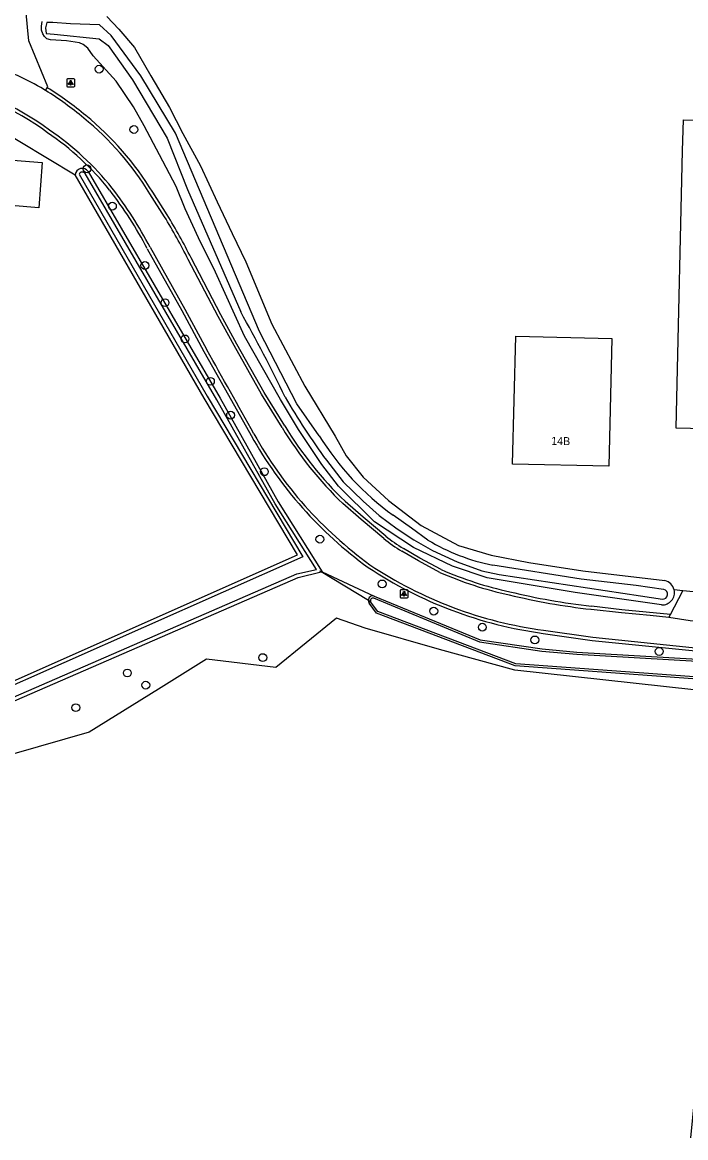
# Model space of a CAD drawing. Extents: x 162515 to 163909, y 388494 to 389773.
# Drawn here: x 162882.1 to 162964.9, y 388907.6 to 389047 of the extents above; entities that cross this region are included whole.
import ezdxf

# ---------------------------------------------------------------- set-up
doc = ezdxf.new("R2010")
doc.units = 0
for name, color, linetype in [('IMGEO_Boom', 7, 'Continuous'), ('IMGEO_Duiker', 7, 'Continuous'), ('IMGEO_Erf', 7, 'Continuous'), ('IMGEO_Grasland_overig', 7, 'Continuous'), ('IMGEO_Lichtpunt', 7, 'Continuous'), ('IMGEO_Pand', 7, 'Continuous'), ('IMGEO_Pand_nummerreeks', 7, 'Continuous'), ('IMGEO_Rijbaan_lokaal_gesloten', 7, 'Continuous'), ('IMGEO_Rijbaan_lokaal_halfverhard', 7, 'Continuous'), ('IMGEO_Rijbaan_lokaal_open', 7, 'Continuous'), ('IMGEO_Waterloop', 7, 'Continuous')]:
    doc.layers.add(name, color=color, linetype=linetype)

msp = doc.modelspace()

# ---------------------------------------------------------------- linework, layer by layer
at = {"layer": 'IMGEO_Boom'}
for centre in [(162891.65, 389041.11), (162895.99, 389033.56), (162890.14, 389028.65), (162893.31, 389023.99), (162897.37, 389016.57), (162899.88, 389011.92), (162902.38, 389007.39), (162905.55, 389002.09), (162908.07, 388997.86), (162912.28, 388990.79), (162919.22, 388982.36), (162927, 388976.77), (162933.44, 388973.37), (162939.51, 388971.36), (162946.06, 388969.77), (162912.09, 388967.56), (162961.59, 388968.33), (162895.18, 388965.64), (162897.48, 388964.12), (162888.74, 388961.31)]:
    msp.add_circle(centre, 0.489, dxfattribs=at)
at = {"layer": 'IMGEO_Duiker'}
msp.add_lwpolyline([(162925.55, 388974.52), (162925.28, 388974.68), (162919.38, 388978.26), (162919.23, 388978.35)], dxfattribs=at)
at = {"layer": 'IMGEO_Erf'}
for points in [[(162892.6, 389047.68), (162894.1, 389046.11), (162896.08, 389043.82), (162898.1, 389040.29), (162900.44, 389036.33), (162902.12, 389033.05), (162904.3, 389029.04), (162906.41, 389024.54), (162908.27, 389020.57), (162909.99, 389017.04), (162913.23, 389009.24), (162917.33, 389001.49), (162921.11, 388995.24), (162922.51, 388992.78), (162924.64, 388990.11), (162927.8, 388987.2), (162931.87, 388984.07), (162936.51, 388981.57), (162940.61, 388980.35), (162945.32, 388979.43), (162952.05, 388978.4), (162962.29, 388977.18)], [(162816.85, 388961.05), (162821.19, 388960.92), (162824.39, 388960.76), (162843.87, 388960.07), (162877.14, 388962.94), (162916.43, 388980.39), (162904.76, 389000), (162888.66, 389027.91)]]:
    msp.add_lwpolyline(points, dxfattribs=at)
msp.add_arc((162961.96, 388975.68), 1.54, 12.9757, 77.6155, dxfattribs=at)
at = {"layer": 'IMGEO_Grasland_overig'}
for points in [[(162961.88, 388974.14), (162951.1, 388975.68), (162940.13, 388977.51), (162935.78, 388978.99), (162930.9, 388981.31), (162926.02, 388984.51), (162921.54, 388989), (162919.45, 388991.71), (162916.57, 388996.05), (162914.29, 388999.84), (162909.82, 389007.73), (162906.18, 389015.74), (162904.05, 389020.03), (162902.41, 389023.63), (162901.28, 389026.43), (162899.19, 389030.38), (162897.29, 389034.04), (162895.94, 389036.38), (162893.79, 389039.62), (162890.91, 389042.76), (162890.23, 389043.72), (162889.65, 389044.2), (162889.21, 389044.4), (162887.56, 389044.65), (162885.56, 389044.78), (162885.13, 389044.91), (162884.83, 389045.18), (162884.63, 389045.54), (162884.47, 389045.97), (162884.45, 389046.48), (162884.52, 389047.05)], [(162878.25, 389034.16), (162888.66, 389027.91)], [(162890.27, 389028.32), (162906.76, 389000), (162914.02, 388987.02), (162919.52, 388978.29)], [(162874.43, 388960.34), (162877.49, 388960.62), (162916.5, 388977.59), (162919.38, 388978.26), (162919.52, 388978.29)], [(162919.52, 388978.29), (162925.98, 388975.25)], [(162925.98, 388975.25), (162939.23, 388969.78), (162946.96, 388968.64), (162951.32, 388968.25), (162966.39, 388967.36), (162970.78, 388966.26), (162971.31, 388964.52), (162972.19, 388961.62)], [(162964.53, 388975.92), (162963.46, 388976.02)], [(162969.72, 388963.11), (162969.19, 388964.66), (162943.62, 388966.52), (162926.27, 388973.12), (162925.38, 388974.38)], [(162969.72, 388963.11), (162943.58, 388965.98), (162934.15, 388968.56), (162924.89, 388971.24), (162921.31, 388972.48), (162913.72, 388966.33), (162905.08, 388967.36), (162899.05, 388963.63), (162890.42, 388958.22), (162881.01, 388955.53), (162875.05, 388956.02), (162874.43, 388960.34)]]:
    msp.add_lwpolyline(points, dxfattribs=at)
for centre, radius, start, end in [((162889.54, 389027.83), 0.884, 33.4629, 174.7096), ((162925.84, 388974.71), 0.565, 75.6448, 182.3466), ((162961.96, 388975.68), 1.54, 267.0987, 12.9137), ((162925.84, 388974.71), 0.565, 182.2245, 214.8736)]:
    msp.add_arc(centre, radius, start, end, dxfattribs=at)
at = {"layer": 'IMGEO_Lichtpunt'}
for p, q in [((162887.61, 389039.81), (162887.61, 389039)), ((162887.61, 389039.81), (162887.61, 389039)), ((162888.51, 389039.9), (162887.7, 389039.9)), ((162888.51, 389039.9), (162887.7, 389039.9)), ((162888.61, 389039), (162888.61, 389039.81)), ((162888.61, 389039), (162888.61, 389039.81)), ((162887.7, 389038.91), (162888.51, 389038.91)), ((162887.7, 389038.91), (162888.51, 389038.91)), ((162929.24, 388975.94), (162929.24, 388975.13)), ((162929.24, 388975.94), (162929.24, 388975.13)), ((162930.14, 388976.03), (162929.33, 388976.03)), ((162930.14, 388976.03), (162929.33, 388976.03)), ((162929.33, 388975.04), (162930.14, 388975.04)), ((162929.33, 388975.04), (162930.14, 388975.04)), ((162930.23, 388975.13), (162930.23, 388975.94)), ((162930.23, 388975.13), (162930.23, 388975.94))]:
    msp.add_line(p, q, dxfattribs=at)
for points in [[(162887.98, 389039.47), (162888.02, 389039.45), (162887.84, 389039.18), (162887.8, 389039.21), (162887.98, 389039.47)], [(162888.09, 389039.43), (162888.13, 389039.43), (162888.13, 389039.1), (162888.09, 389039.1), (162888.09, 389039.43)], [(162888.2, 389039.45), (162888.23, 389039.47), (162888.42, 389039.21), (162888.38, 389039.18), (162888.2, 389039.45)], [(162929.61, 388975.6), (162929.65, 388975.57), (162929.46, 388975.31), (162929.42, 388975.34), (162929.61, 388975.6)], [(162929.71, 388975.55), (162929.76, 388975.55), (162929.76, 388975.23), (162929.71, 388975.23), (162929.71, 388975.55)], [(162929.82, 388975.57), (162929.86, 388975.6), (162930.05, 388975.34), (162930.01, 388975.31), (162929.82, 388975.57)]]:
    msp.add_lwpolyline(points, dxfattribs=at)
for centre in [(162888.11, 389039.61), (162929.74, 388975.74)]:
    msp.add_circle(centre, 0.0994, dxfattribs=at)
for centre, start, end in [((162887.7, 389039.81), 90, 180), ((162887.7, 389039.81), 90, 180), ((162887.7, 389039), 180, 270), ((162887.7, 389039), 180, 270), ((162888.51, 389039.81), 0, 90), ((162888.51, 389039.81), 0, 90), ((162888.51, 389039), 270, 0), ((162888.51, 389039), 270, 360), ((162929.33, 388975.94), 90, 180), ((162929.33, 388975.94), 90, 180), ((162929.33, 388975.13), 180, 270), ((162929.33, 388975.13), 180, 270), ((162930.14, 388975.94), 0, 90), ((162930.14, 388975.94), 0, 90), ((162930.14, 388975.13), 270, 0), ((162930.14, 388975.13), 270, 360)]:
    msp.add_arc(centre, 0.0946, start, end, dxfattribs=at)
at = {"layer": 'IMGEO_Pand'}
for points in [[(162964.61, 389034.78), (162973.6, 389034.57), (162973.51, 389030.67), (162972.8, 389000), (162972.71, 388996.01), (162963.71, 388996.22), (162963.8, 389000), (162964.52, 389030.88), (162964.61, 389034.78)], [(162867.03, 389021.53), (162867.2, 389023.58), (162863, 389023.94), (162863.17, 389026.12), (162863.56, 389031.1), (162884.55, 389029.46), (162884.11, 389023.77), (162876.68, 389024.39), (162876.61, 389023.5), (162874.12, 389023.71), (162873.89, 389020.95), (162868.91, 389021.37), (162867.03, 389021.53)], [(162955.68, 389007.46), (162955.3, 388991.47), (162943.29, 388991.75), (162943.67, 389007.75), (162955.68, 389007.46)]]:
    msp.add_lwpolyline(points, dxfattribs=at)
at = {"layer": 'IMGEO_Rijbaan_lokaal_gesloten'}
for points in [[(162884.97, 389038.44), (162884.37, 389038.8)], [(162899.81, 389022.67), (162898, 389025.53)], [(162898.02, 389018.85), (162902.34, 389011.12), (162905.09, 389006.01)], [(162914.49, 388996.32), (162911.93, 389000.49), (162908.5, 389006.55), (162906.52, 389010.2), (162902.78, 389017.33)], [(162927.2, 388982.44), (162924.36, 388984.82), (162922.1, 388986.8)], [(162934.19, 388978.21), (162931.52, 388979.64), (162929.45, 388980.86)], [(162962.8, 388972.56), (162960.47, 388972.81), (162956.88, 388973.14), (162953.08, 388973.59)], [(162985.33, 388970.8), (162980.07, 388971.13), (162974.83, 388971.46), (162970.89, 388971.74), (162967.25, 388972), (162965.45, 388972.17), (162962.8, 388972.56)], [(162947.16, 388970.98), (162953.29, 388970.1), (162965.73, 388968.84), (162970.17, 388968.56)]]:
    msp.add_lwpolyline(points, dxfattribs=at)
for centre, radius, start, end in [((162869.12, 389012.67), 30.25, 59.7395, 73.9437), ((162864.06, 389004.38), 36.13, 53.6844, 78.3393), ((162861.7, 389001.29), 43.84, 50.2578, 57.9413), ((162866.42, 389006.29), 36.98, 31.3496, 50.9245), ((162864.72, 389003.25), 36.67, 38.8444, 55.5582), ((162851.18, 388994.02), 53.02, 27.9198, 37.4324), ((162836.83, 388984.19), 73.8, 26.6823, 31.4251), ((162110.11, 388552.61), 915.19, 28.94362, 29.69779), ((162953.57, 389019.74), 45.55, 210.9339, 226.302), ((162955.27, 389020.16), 50.68, 209.1032, 233.9931), ((162938.63, 388996.36), 18.02, 230.5858, 239.3414), ((162954.15, 389022.32), 51.82, 236.4029, 262.2535), ((162952.77, 389020.73), 46.4, 246.3989, 257.6586), ((162962.76, 389058.13), 85.09, 256.4655, 263.4636)]:
    msp.add_arc(centre, radius, start, end, dxfattribs=at)
at = {"layer": 'IMGEO_Rijbaan_lokaal_halfverhard'}
for points in [[(162900.15, 389022.88), (162898.35, 389025.74)], [(162897.67, 389018.67), (162901.99, 389010.93), (162904.73, 389005.83), (162907.82, 389000.37), (162910.64, 388995.32)], [(162914.84, 388996.53), (162912.28, 389000.69), (162908.85, 389006.75), (162906.87, 389010.39), (162903.14, 389017.51)], [(162927.45, 388982.75), (162924.62, 388985.13), (162922.37, 388987.09)], [(162934.38, 388978.56), (162931.71, 388979.99), (162929.65, 388981.21)], [(162963, 388972.94), (162956.93, 388973.53), (162953.12, 388973.99)], [(162947.11, 388970.58), (162953.24, 388969.71), (162965.69, 388968.45), (162970.16, 388968.16)]]:
    msp.add_lwpolyline(points, dxfattribs=at)
for centre, radius, start, end in [((162863.8, 389003.95), 36.23, 53.7471, 78.0279), ((162861.7, 389001.28), 44.25, 50.2646, 57.9478), ((162866.37, 389006.25), 37.44, 31.3636, 50.9013), ((162864.71, 389003.24), 36.28, 38.8417, 55.5726), ((162851.34, 388994.13), 52.43, 27.9152, 37.4382), ((162836.7, 388984.12), 74.36, 26.6858, 31.4234), ((162953.54, 389019.71), 45.11, 210.9169, 226.305), ((162955.29, 389020.18), 51.11, 209.1102, 233.9853), ((162938.62, 388996.34), 17.59, 230.6015, 239.355), ((162954.14, 389022.3), 52.19, 236.3797, 262.2598), ((162952.82, 389020.91), 46.19, 246.4742, 257.6471), ((162962.81, 389058.39), 84.96, 256.4683, 263.451)]:
    msp.add_arc(centre, radius, start, end, dxfattribs=at)
at = {"layer": 'IMGEO_Rijbaan_lokaal_open'}
for points in [[(162885.18, 389038.78), (162885.25, 389038.88), (162882.86, 389044.66), (162882.71, 389046.36), (162882.55, 389048.13)], [(162884.97, 389038.44), (162885.18, 389038.78)], [(162963, 388972.94), (162964.53, 388975.92)], [(162985.53, 388974.35), (162971.11, 388975.28), (162964.53, 388975.92)], [(162962.8, 388972.56), (162963, 388972.94)]]:
    msp.add_lwpolyline(points, dxfattribs=at)
at = {"layer": 'IMGEO_Waterloop'}
for points in [[(162901.2, 389033.09), (162896.85, 389040.28), (162893.17, 389045.33), (162891.71, 389046.64), (162888.08, 389046.77), (162885.86, 389046.92), (162885.14, 389046.92), (162884.95, 389046.26), (162885.05, 389045.56), (162886.02, 389045.48), (162891.65, 389044.89), (162892.8, 389044.06), (162895.84, 389039.79), (162900.15, 389032.48), (162902.67, 389026.07), (162909.33, 389010.77)], [(162919.15, 388995.28), (162916.35, 388999.29), (162911.67, 389008.33), (162901.2, 389033.09)], [(162889.15, 389027.99), (162905.16, 389000.23), (162917.09, 388980.17), (162877.26, 388962.48), (162843.88, 388959.6), (162823.98, 388960.31), (162821.65, 388960.44), (162816.83, 388960.59), (162780.2, 388961.67), (162780.24, 388960.68), (162787.1, 388960.37), (162830.42, 388958.42), (162844.31, 388958.04), (162877.38, 388961.07)], [(162877.38, 388961.07), (162916.35, 388978.03), (162918.78, 388978.59), (162913.62, 388986.78), (162906.36, 388999.77), (162889.89, 389028.06)], [(162920.04, 388992.23), (162922.11, 388989.51), (162924.63, 388987.13), (162926.62, 388985.32), (162928.87, 388983.66), (162930.97, 388982.26), (162933.29, 388980.94), (162936.36, 388979.52), (162939.44, 388978.42), (162941.61, 388977.93), (162959.25, 388975.27), (162962, 388974.86)], [(162932.72, 388982.25), (162930.67, 388983.75), (162928.37, 388985.35)], [(162962.15, 388976.07), (162958.7, 388976.56), (162951.84, 388977.36), (162940.81, 388979.11)], [(162925.91, 388975.01), (162939.16, 388969.53), (162946.93, 388968.38), (162951.3, 388968), (162966.35, 388967.11), (162970.58, 388966.04), (162971.06, 388964.44), (162971.93, 388961.6), (162966.53, 388908.21)], [(162965.55, 388907.55), (162970.77, 388960.85), (162969.96, 388963.2), (162969.38, 388964.9), (162943.67, 388966.77), (162926.44, 388973.33), (162925.55, 388974.52)]]:
    msp.add_lwpolyline(points, dxfattribs=at)
for centre, radius, start, end in [((162889.54, 389027.83), 0.419, 31.878, 158.3999), ((162742.42, 388917.06), 191.42, 25.7159, 29.3125), ((162985.08, 389040.41), 80.94, 209.8507, 216.5282), ((162948.73, 389013.52), 34.75, 211.6516, 234.131), ((162945.92, 389004.26), 25.67, 239.0483, 258.5136), ((162925.86, 388974.67), 0.341, 80.6653, 206.1249), ((162962.03, 388975.47), 0.611, 267.6133, 78.0433)]:
    msp.add_arc(centre, radius, start, end, dxfattribs=at)

# ---------------------------------------------------------------- texts
at = {"layer": 'IMGEO_Pand_nummerreeks'}
msp.add_text('14B', height=1, rotation=358.6368, dxfattribs=at).set_placement((162948.09, 388994.16))

doc.saveas('drawing.dxf')
